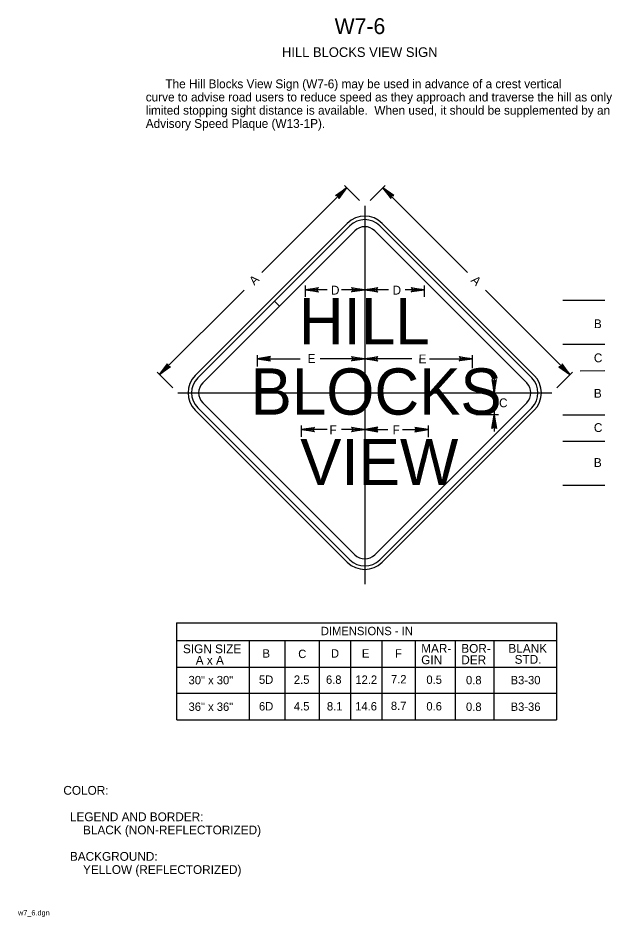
# Model space of a CAD drawing. Extents: x 0.013 to 0.181, y 0.004 to 0.259.
import ezdxf

# ---------------------------------------------------------------- set-up
doc = ezdxf.new("R2010")
doc.units = 0
for name, color, linetype in [('1', 7, 'Continuous'), ('2', 7, 'Continuous'), ('3', 7, 'Continuous')]:
    doc.layers.add(name, color=color, linetype=linetype)

# ---------------------------------------------------------------- blocks, each defined once
blk = doc.blocks.new('RARROW')
at = {"layer": '3'}
for p, q in [((-2.156, 0.285), (-2.2665, 0.384625)), ((-2.2665, 0.384625), (0, 0)), ((0, 0), (-2.2665, -0.379125)), ((-2.156, 0.285), (-2.075625, 0.12075)), ((0, 0), (-2.156, 0.285)), ((-2.14975, -0.2705), (0, 0)), ((-2.075625, 0.12075), (0, 0)), ((0, 0), (-2.074, -0.108)), ((-2.2665, -0.379125), (-2.14975, -0.2705)), ((-2.074, -0.108), (-2.14975, -0.2705))]:
    blk.add_line(p, q, dxfattribs=at)

msp = doc.modelspace()

# ---------------------------------------------------------------- linework, layer by layer
at = {"layer": '1'}
for p, q in [((0.11101, 0.20573), (0.11101, 0.09841)), ((0.10606, 0.20078), (0.06293, 0.15765)), ((0.10677, 0.20008), (0.08536, 0.17867)), ((0.15839, 0.15694), (0.11525, 0.20008)), ((0.15909, 0.15765), (0.11596, 0.20078)), ((0.14142, 0.17533), (0.11596, 0.20078)), ((0.08678, 0.17726), (0.10818, 0.19866)), ((0.11384, 0.19866), (0.15697, 0.15553)), ((0.09411, 0.18315), (0.09411, 0.17992)), ((0.12791, 0.18315), (0.12791, 0.17992)), ((0.08536, 0.17867), (0.06363, 0.15694)), ((0.08678, 0.17726), (0.08536, 0.17867)), ((0.08536, 0.17867), (0.08678, 0.17726)), ((0.06505, 0.15553), (0.08678, 0.17726)), ((0.08051, 0.16339), (0.08051, 0.16015)), ((0.14151, 0.16339), (0.14151, 0.15967)), ((0.14774, 0.15847), (0.14774, 0.1417)), ((0.0623, 0.157), (0.0623, 0.157)), ((0.06363, 0.14846), (0.10677, 0.10533)), ((0.10818, 0.10674), (0.06505, 0.14987)), ((0.15697, 0.14987), (0.11384, 0.10674)), ((0.11525, 0.10533), (0.15839, 0.14846)), ((0.10606, 0.10462), (0.06293, 0.14775)), ((0.15909, 0.14775), (0.11596, 0.10462)), ((0.09301, 0.14343), (0.09301, 0.14019)), ((0.12901, 0.14343), (0.12901, 0.14007))]:
    msp.add_line(p, q, dxfattribs=at)
for centre, radius, start, end in [((0.11101, 0.19583), 0.007, 45, 135), ((0.11101, 0.19583), 0.006, 45, 135), ((0.11101, 0.19583), 0.004, 45, 135), ((0.06788, 0.1527), 0.007, 135, 225), ((0.06788, 0.1527), 0.006, 135, 225), ((0.15414, 0.1527), 0.006, 315, 45), ((0.15414, 0.1527), 0.007, 315, 45), ((0.06788, 0.1527), 0.004, 135, 225), ((0.15414, 0.1527), 0.004, 315, 45), ((0.11101, 0.10957), 0.007, 225, 315), ((0.11101, 0.10957), 0.006, 225, 315), ((0.11101, 0.10957), 0.004, 225, 315)]:
    msp.add_arc(centre, radius, start, end, dxfattribs=at)
at = {"layer": '3'}
for p, q in [((0.10584, 0.21088), (0.08182, 0.18685)), ((0.1095, 0.20723), (0.10523, 0.21149)), ((0.11252, 0.20723), (0.11679, 0.21149)), ((0.11618, 0.21088), (0.1402, 0.18685)), ((0.07679, 0.18182), (0.05281, 0.15785)), ((0.10034, 0.18192), (0.09411, 0.18192)), ((0.11101, 0.18192), (0.10442, 0.18192)), ((0.11777, 0.18192), (0.11101, 0.18192)), ((0.12791, 0.18192), (0.12244, 0.18192)), ((0.14524, 0.18182), (0.16921, 0.15785)), ((0.16718, 0.17896), (0.1791, 0.17898)), ((0.16719, 0.16646), (0.17911, 0.16648)), ((0.08051, 0.16234), (0.09265, 0.16234)), ((0.11101, 0.16234), (0.0984, 0.16234)), ((0.12439, 0.16234), (0.11101, 0.16234)), ((0.12942, 0.16234), (0.14151, 0.16234)), ((0.05654, 0.15412), (0.0521, 0.15856)), ((0.16548, 0.15412), (0.16992, 0.15856)), ((0.17211, 0.15897), (0.17912, 0.15898)), ((0.05796, 0.1527), (0.16408, 0.1527)), ((0.14899, 0.14646), (0.14252, 0.14646)), ((0.16721, 0.14646), (0.17913, 0.14648)), ((0.10034, 0.14227), (0.09301, 0.14227)), ((0.11101, 0.14227), (0.10442, 0.14227)), ((0.11101, 0.14227), (0.1176, 0.14227)), ((0.12168, 0.14227), (0.12901, 0.14227)), ((0.16722, 0.13896), (0.17914, 0.13898)), ((0.16723, 0.12646), (0.17916, 0.12648)), ((0.05764, 0.08741), (0.1654, 0.08741)), ((0.05764, 0.08741), (0.05764, 0.05987)), ((0.1654, 0.08229), (0.05764, 0.08229)), ((0.07826, 0.08229), (0.07826, 0.05987)), ((0.09809, 0.08229), (0.09809, 0.05987)), ((0.13668, 0.08229), (0.13668, 0.05987)), ((0.14761, 0.08229), (0.14761, 0.05987)), ((0.05764, 0.07479), (0.1654, 0.07479)), ((0.05765, 0.06741), (0.1654, 0.06741)), ((0.05765, 0.05987), (0.1654, 0.05987))]:
    msp.add_line(p, q, dxfattribs=at)
for points in [[(0.1654, 0.08741), (0.1654, 0.05987)], [(0.08829, 0.08229), (0.08829, 0.05987)], [(0.10695, 0.08229), (0.10695, 0.05987)], [(0.11588, 0.08229), (0.11588, 0.05987)], [(0.12529, 0.08229), (0.12529, 0.05987)]]:
    msp.add_lwpolyline(points, dxfattribs=at)

# ---------------------------------------------------------------- block references
for p, xscale, yscale, rotation in [((0.10584, 0.21088), 0.0016545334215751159, 0.0016366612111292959, 44.91708286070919), ((0.11618, 0.21088), 0.0016545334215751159, -0.0016366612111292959, 135.08291713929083), ((0.09411, 0.18192), 0.0016545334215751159, 0.0016366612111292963, 179.91708286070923), ((0.11101, 0.18192), 0.0016545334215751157, 0.001636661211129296, -0.08291713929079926), ((0.11101, 0.18192), 0.0016545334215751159, 0.0016366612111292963, 179.91708286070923), ((0.12791, 0.18192), 0.0016545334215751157, 0.001636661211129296, -0.08291713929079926), ((0.05281, 0.15785), 0.001654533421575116, 0.001636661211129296, -135.0829171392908), ((0.08051, 0.16234), 0.0016545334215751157, -0.001636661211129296, -179.9170828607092), ((0.11101, 0.16234), 0.0016545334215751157, 0.001636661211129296, -0.08291713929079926), ((0.11101, 0.16234), 0.0016545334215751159, 0.0016366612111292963, 179.91708286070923), ((0.14151, 0.16234), 0.0016545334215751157, 0.001636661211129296, -0.08291713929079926), ((0.16921, 0.15785), 0.001654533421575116, -0.001636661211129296, -44.917082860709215), ((0.14774, 0.1527), 0.0016545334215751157, -0.001636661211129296, -89.9170828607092), ((0.14774, 0.14633), 0.0016545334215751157, 0.001636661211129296, 89.9170828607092), ((0.09301, 0.14227), 0.0016545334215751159, 0.0016366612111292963, 179.91708286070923), ((0.11101, 0.14227), 0.0016545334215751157, 0.001636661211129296, -0.08291713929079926), ((0.11101, 0.14227), 0.0016545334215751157, -0.001636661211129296, -179.9170828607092), ((0.12901, 0.14227), 0.0016545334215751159, -0.0016366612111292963, 0.08291713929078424)]:
    msp.add_blockref('RARROW', p, dxfattribs=dict(at, xscale=xscale, yscale=yscale, rotation=rotation))

# ---------------------------------------------------------------- texts
at = {"layer": '1'}
for s, height, p in [('W7-6', 0.0045, (0.10246, 0.2545)), ('HILL BLOCKS VIEW SIGN', 0.0027503, (0.08752, 0.248)), ('HILL', 0.013133, (0.09234, 0.16644)), ('BLOCKS', 0.013133, (0.07861, 0.14649)), ('VIEW', 0.013133, (0.09268, 0.12649)), ('COLOR:', 0.0025, (0.0255, 0.03862)), ('  LEGEND AND BORDER:', 0.0024998, (0.0255, 0.03112)), ('      BLACK (NON-REFLECTORIZED)', 0.0024998, (0.0255, 0.02738)), ('  BACKGROUND:', 0.0024998, (0.0255, 0.01988)), ('      YELLOW (REFLECTORIZED)', 0.0024998, (0.0255, 0.01613)), ('w7_6.dgn', 0.0015, (0.01263, 0.00438))]:
    msp.add_text(s, height=height, dxfattribs=at).set_placement(p)
at = {"layer": '2'}
for s, p in [('      The Hill Blocks View Sign (W7-6) may be used in advance of a crest vertical', (0.04888, 0.23913)), ('curve to advise road users to reduce speed as they approach and traverse the hill as only', (0.04888, 0.23538)), ('limited stopping sight distance is available.  When used, it should be supplemented by an', (0.04888, 0.23163)), ('Advisory Speed Plaque (W13-1P).', (0.04888, 0.22788))]:
    msp.add_text(s, height=0.0024998, dxfattribs=at).set_placement(p)
at = {"layer": '3'}
for s, rotation, p in [('A', 44.9171, (0.07969, 0.18307)), ('A', 315.0829, (0.14097, 0.18442)), ('D', 359.9171, (0.10142, 0.18058)), ('D', 0.0829, (0.11891, 0.18058)), ('B', 359.9171, (0.17602, 0.17104)), ('E', 0.0829, (0.0948, 0.16118)), ('E', 359.9171, (0.12627, 0.16106)), ('C', 0.0829, (0.17602, 0.16136)), ('B', 0.0829, (0.17602, 0.1513)), ('C', 0.0829, (0.14912, 0.1486)), ('F', 359.9171, (0.101, 0.14093)), ('F', 0.0829, (0.1189, 0.14093)), ('C', 359.9171, (0.17602, 0.14157)), ('B', 0.0829, (0.17602, 0.13165))]:
    msp.add_text(s, height=0.0025, rotation=rotation, dxfattribs=at).set_placement(p)
for s, height, p in [('DIMENSIONS - IN', 0.0023752, (0.09856, 0.08391)), ('SIGN SIZE', 0.0025, (0.05944, 0.07879)), ('B', 0.00238, (0.082, 0.07754)), ('C', 0.00238, (0.09214, 0.07741)), ('D', 0.00238, (0.10142, 0.07754)), ('E', 0.00238, (0.1102, 0.07754)), ('F', 0.00238, (0.1196, 0.07754)), ('MAR-', 0.0025, (0.12703, 0.07891)), ('BOR-', 0.0025, (0.1384, 0.07891)), ('BLANK', 0.0025, (0.15178, 0.07891)), ('A x A', 0.0025, (0.06305, 0.07554)), ('GIN', 0.0025, (0.12703, 0.07566)), ('DER', 0.0025, (0.1384, 0.07566)), ('STD.', 0.0025, (0.15353, 0.07579)), ('30" x 30"', 0.002375, (0.06102, 0.06997)), ('5D', 0.002375, (0.081, 0.0701)), ('2.5', 0.002375, (0.0909, 0.0701)), ('6.8', 0.002375, (0.10001, 0.0701)), ('12.2', 0.002375, (0.10835, 0.0701)), ('7.2', 0.002375, (0.11845, 0.07022)), ('0.5', 0.002375, (0.1285, 0.07009)), ('0.8', 0.002375, (0.13974, 0.06997)), ('B3-30', 0.002375, (0.1524, 0.06997)), ('36" x 36"', 0.002375, (0.06102, 0.06242)), ('6D', 0.002375, (0.081, 0.06254)), ('4.5', 0.002375, (0.0909, 0.06254)), ('8.1', 0.002375, (0.10027, 0.06254)), ('14.6', 0.002375, (0.1083, 0.06254)), ('8.7', 0.002375, (0.11843, 0.06267)), ('0.6', 0.002375, (0.1285, 0.06254)), ('0.8', 0.002375, (0.13974, 0.06241)), ('B3-36', 0.002375, (0.1524, 0.06242))]:
    msp.add_text(s, height=height, dxfattribs=at).set_placement(p)

doc.saveas('drawing.dxf')
